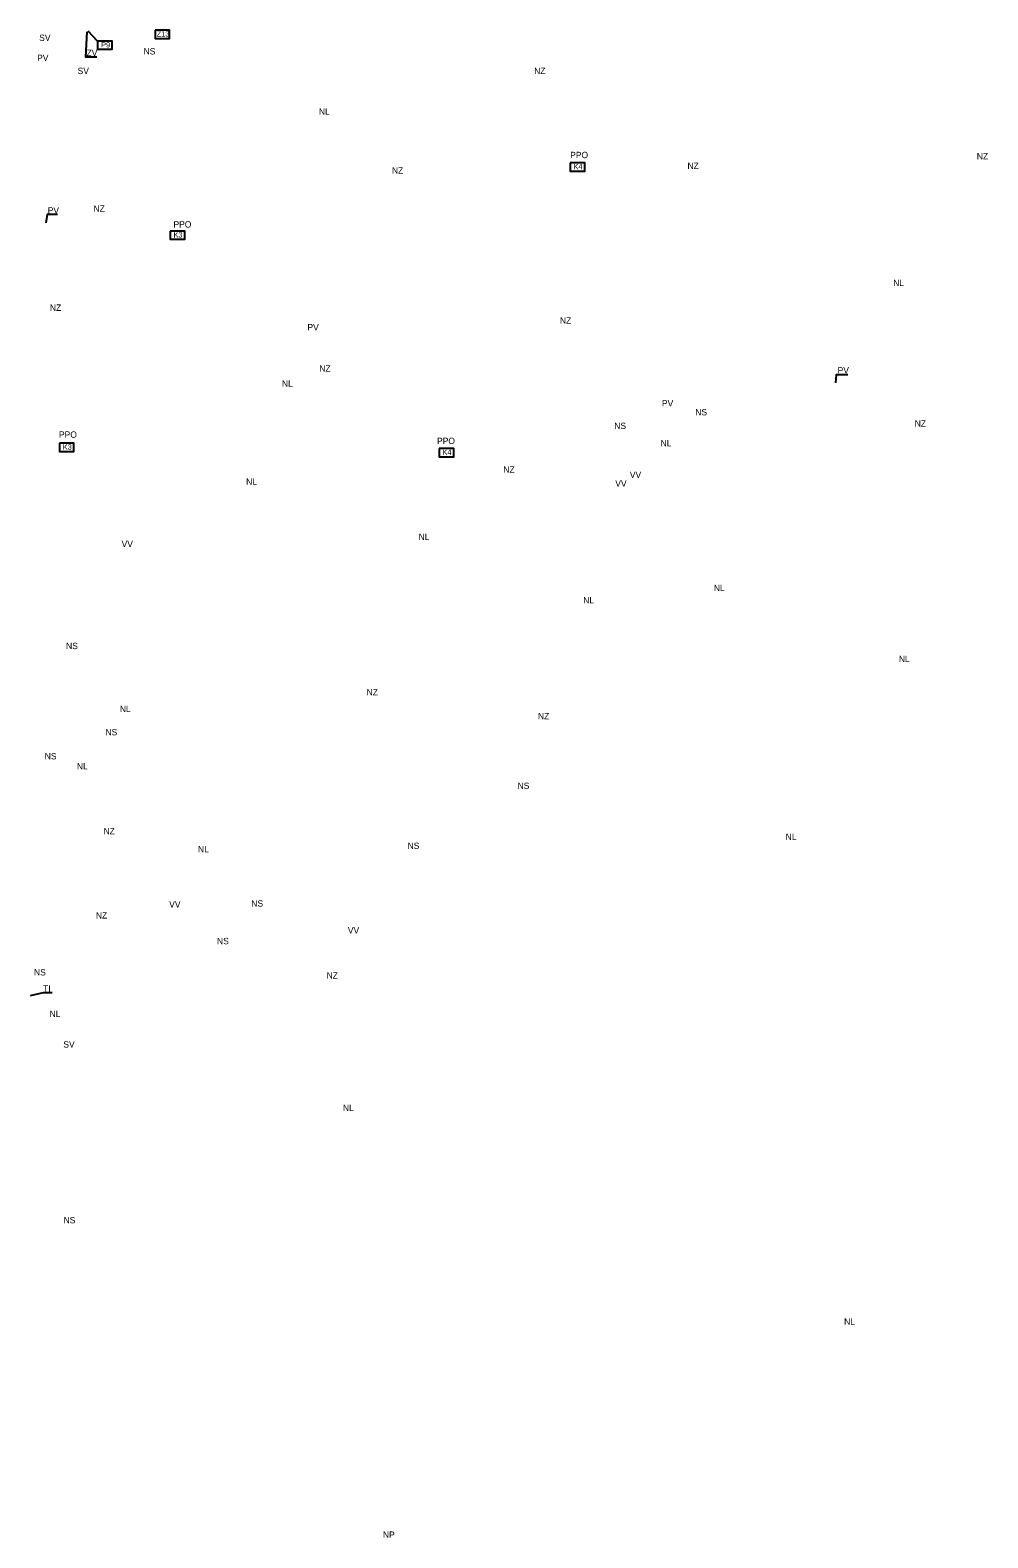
# Model space of a CAD drawing. Extents: x -546576 to -528254, y -1046225 to -1035772.
# Drawn here: x -543266 to -541456, y -1043164 to -1040314 of the extents above; entities that cross this region are included whole.
import ezdxf

# ---------------------------------------------------------------- set-up
doc = ezdxf.new("R2010")
doc.units = 0
for name, color, linetype in [('Vrstva 10', 7, 'Continuous'), ('Vrstva 11', 7, 'Continuous'), ('Vrstva 3', 7, 'Continuous'), ('Vrstva 4', 7, 'Continuous'), ('Vrstva 7', 7, 'Continuous')]:
    doc.layers.add(name, color=color, linetype=linetype)

msp = doc.modelspace()

# ---------------------------------------------------------------- linework, layer by layer
at = {"layer": 'Vrstva 10'}
for points in [[(-543140.2, -1040365.6), (-543161, -1040365.6), (-543158, -1040317.4)], [(-543214.2, -1040662.9), (-543233.6, -1040662.9), (-543236.2, -1040678.4)], [(-541720.4, -1040966.1), (-541742.4, -1040966.1), (-541743.7, -1040981.1)], [(-543224.5, -1042134.3), (-543241.1, -1042134.3), (-543266, -1042139.5)]]:
    msp.add_lwpolyline(points, dxfattribs=at)
at = {"layer": 'Vrstva 3'}
msp.add_lwpolyline([(-543029.8, -1040314.4), (-543029.8, -1040330), (-543002.3, -1040330), (-543002.3, -1040314.4), (-543029.8, -1040314.4)], dxfattribs=at)
at = {"layer": 'Vrstva 4'}
msp.add_line((-543138.6, -1040335), (-543156.5, -1040316.3), dxfattribs=at)
msp.add_lwpolyline([(-543138.6, -1040335), (-543138.6, -1040350.6), (-543111.1, -1040350.6), (-543111.1, -1040335), (-543138.6, -1040335)], dxfattribs=at)
at = {"layer": 'Vrstva 7'}
for points in [[(-542245, -1040565.4), (-542245, -1040580.9), (-542217.5, -1040580.9), (-542217.5, -1040565.4), (-542245, -1040565.4)], [(-543001.4, -1040694.3), (-543001.4, -1040709.8), (-542973.9, -1040709.8), (-542973.9, -1040694.3), (-543001.4, -1040694.3)], [(-543210.7, -1041095.3), (-543210.7, -1041110.8), (-543183.2, -1041110.8), (-543183.2, -1041095.3), (-543210.7, -1041095.3)], [(-542492.6, -1041105.2), (-542492.6, -1041120.7), (-542465.1, -1041120.7), (-542465.1, -1041105.2), (-542492.6, -1041105.2)]]:
    msp.add_lwpolyline(points, dxfattribs=at)

# ---------------------------------------------------------------- texts
at = {"layer": 'Vrstva 10'}
for s, p in [('SV', (-543248.9, -1040334.8)), ('PV', (-543252.8, -1040372.8)), ('ZV', (-543159.4, -1040363.4)), ('NS', (-543051.6, -1040360.4)), ('SV', (-543176.3, -1040397.5)), ('NZ', (-542313.2, -1040397.3)), ('NL', (-542720.1, -1040474.4)), ('NZ', (-542023.4, -1040576.8)), ('NZ', (-541476.4, -1040558.8)), ('NZ', (-542582, -1040585.5)), ('PV', (-543232.8, -1040661.1)), ('NZ', (-543146.3, -1040657.8)), ('NL', (-541634.5, -1040797.8)), ('NZ', (-543228.6, -1040845)), ('PV', (-542741.8, -1040881.9)), ('NZ', (-542264.4, -1040869.2)), ('NZ', (-542719.3, -1040959.9)), ('PV', (-541739.5, -1040963.4)), ('NL', (-542790, -1040988.5)), ('PV', (-542071.6, -1041025.7)), ('NS', (-542008.6, -1041042.5)), ('NZ', (-541593.7, -1041063.8)), ('NS', (-542161.7, -1041068.4)), ('NL', (-542074.2, -1041101.1)), ('NL', (-542857.7, -1041173.8)), ('NZ', (-542371.4, -1041151.1)), ('VV', (-542159.8, -1041177.3)), ('VV', (-542132.3, -1041161)), ('VV', (-543093.1, -1041291.5)), ('NL', (-542531.7, -1041278)), ('NL', (-541973.5, -1041374.8)), ('NL', (-542220.4, -1041398.1)), ('NS', (-543198.1, -1041484.4)), ('NL', (-541623.8, -1041508.7)), ('NZ', (-542629.9, -1041571.9)), ('NL', (-543096.5, -1041603.2)), ('NZ', (-542305.9, -1041616.9)), ('NZ', (-542305.9, -1041616.9)), ('NS', (-543123.6, -1041647.4)), ('NS', (-543238.4, -1041692.9)), ('NL', (-543177.6, -1041711.9)), ('NS', (-542344.5, -1041748.7)), ('NZ', (-543127.3, -1041834.3)), ('NS', (-542552.4, -1041862.1)), ('NL', (-541837.7, -1041845.5)), ('NL', (-542948.6, -1041868.7)), ('VV', (-543003.1, -1041972.9)), ('VV', (-543003.1, -1041972.9)), ('NS', (-542847.9, -1041971.1)), ('NZ', (-543141.8, -1041993.6)), ('VV', (-542665.4, -1042021.9)), ('NS', (-542912.8, -1042042.2)), ('NS', (-543258.7, -1042101.2)), ('NZ', (-542705.5, -1042107.1)), ('TI', (-543241.5, -1042132.1)), ('NL', (-543229.3, -1042179.6)), ('SV', (-543203.3, -1042237.5)), ('NL', (-542674.6, -1042357.7)), ('NS', (-543202.8, -1042569.7)), ('NL', (-541727.2, -1042761.3)), ('NP', (-542599, -1043164.2))]:
    msp.add_text(s, height=12, dxfattribs=at).set_placement(p)
at = {"layer": 'Vrstva 11'}
for p in [(-542245.1, -1040556.4), (-542995.1, -1040687.6), (-543211.5, -1041084.9), (-542496.8, -1041096.8)]:
    msp.add_text('PPO', height=12, dxfattribs=at).set_placement(p)
at = {"layer": 'Vrstva 3'}
msp.add_text('Z13', height=10, dxfattribs=at).set_placement((-543026.7, -1040326.5))
at = {"layer": 'Vrstva 4'}
msp.add_text('P9', height=10, dxfattribs=at).set_placement((-543131.7, -1040347.1))
at = {"layer": 'Vrstva 7'}
for s, p in [('K4', (-542238.8, -1040577.4)), ('K3', (-542994.9, -1040706.4)), ('K3', (-543204.3, -1041107.4)), ('K4', (-542486.4, -1041117.2))]:
    msp.add_text(s, height=10, dxfattribs=at).set_placement(p)

doc.saveas('drawing.dxf')
